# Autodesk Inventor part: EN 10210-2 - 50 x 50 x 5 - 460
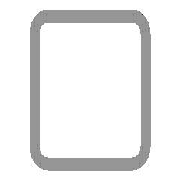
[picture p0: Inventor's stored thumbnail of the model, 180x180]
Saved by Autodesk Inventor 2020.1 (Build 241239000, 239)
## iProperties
_CCFamilyMember: 16
_CCFamilyDisplayName: DIN EN 10210-2 (USAS B17.1 quadratisch) - Rohrleitung — In Klammern angegebene Größen wurden aufgehoben
_FrameMemberDoc: Frame Member File
_Version: 15.0.0
_GetPNFromCC: 1
IsCustomPart: 1
Created: 2019-01
Part Number: EN 10210-2 - 50 x 50 x 5 - 460
Material: Stahl, weich
Description: Rohrleitung
Document SubType Name: Modeling
Standard: DIN
Designer: lutzd
Standard Revision: 2006-07
Standards Organization: DIN
Language: de-DE
Size Designation: 50 x 50 x 5
Categories: <MemberInstance><Categories><Category DisplayName="Profile" InternalName="089c4875-fa83-4c05-b084-43b9cc11f5ed" Mnemonic="GRDR"><CategoryParameter DisplayName="
Stock Number: 50 x 50 x 5
Mass: 3150.31 g
Surface Area: 1575.45 cm^2
Volume: 401.313 cm^3
Density: 7.85 g/cm^3
Appearance: Halbpoliert
G_L: 460,000 mm
G_W: 50,000 mm
G_H: 50,000 mm
DocNumber: ADSK-014081
Folder: .
Dimensions: 50x50x460 mm
Mass: 3,15 kg
+C3927D04-EFA9-4B3D-8386-313517081704+SCHNITTDETAIL1: Schnittwinkel 90,00 grd
Title: Profil-Bauteil
Author: lutzd
Revision Number: -
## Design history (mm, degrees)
node "Startebene"
node "Endebene"
sketch "Skizze"
  geometry: L1 (-25, -17.5)-(-25, 17.5); L2 (-17.5, 25)-(17.5, 25); L3 (25, 17.5)-(25, -17.5); L4 (17.5, -25)-(-17.5, -25); L5 (-15, 20)-(15, 20); L6 (20, 15)-(20, -15); L7 (15, -20)-(-15, -20); L8 (-20, -15)-(-20, 15); L9 (0, 37.175)-(0, -37.175) reference; L10 (-37.175, 0)-(37.175, 0) reference; A1 r 7.5 centre (-17.5, -17.5) between (-25, -17.5) and (-17.5, -25); A2 r 7.5 centre (-17.5, 17.5) between (-17.5, 25) and (-25, 17.5); A3 r 7.5 centre (17.5, 17.5) between (25, 17.5) and (17.5, 25); A4 r 7.5 centre (17.5, -17.5) between (17.5, -25) and (25, -17.5); A5 r 5 centre (-15, -15) between (-20, -15) and (-15, -20); A6 r 5 centre (-15, 15) between (-15, 20) and (-20, 15); A7 r 5 centre (15, 15) between (20, 15) and (15, 20); A8 r 5 centre (15, -15) between (15, -20) and (20, -15)
  constraints: 16 end point, 16 point on circle, 16 tangent, 8 centre point, 6 equal radius, 4 parallel, 2 perpendicular, 2 other
  dimensions: "d7" = 7.5 radius of A1 (= G_IR); "d10" = 50 distance between parallel lines of L2 L4 (= G_H); "d11" = 50 distance between parallel lines of L1 L3 (= G_W); "d12" = 5 distance between parallel lines of L3 L6 (= G_T); "d15" = 25 distance between parallel lines of L2 L10 (= 0.5 x d10); "d16" = 25 distance between parallel lines of L9 L3 (= 0.5 x d11); "d19" = 5 radius of A5 (= G_T); "d20" = 5 distance between parallel lines of L4 L7 (= G_T)
extrude "Körper" new body sketch "Skizze" stored distance "d3" = 460 (= G_L); taper "d4" = 0 deg
node "Driven Length"
  sketch "Sketch3"
    geometry: L1 (0, 0)-(10, 0) reference
    constraints: 2 end point, 1 horizontal
  workplane "Work Plane3"
  sketch "Sketch4"
    geometry: L1 (-2, 25)-(12, 25) reference; L2 (-2, 485)-(12, 485) reference
    dimensions: "d18" = 460 distance between parallel lines of L1 L2 (derived)
workplane "Arbeitsebene4"
feature "Trennen1"
sketch "Skizze5"
  geometry: L1 (0, -35)-(0, 0) reference; L2 (0, -17.5)-(321, -17.5); 3 further points
  constraints: 2 end point, 1 coincident, 1 horizontal, 1 midpoint, 1 point on line
  dimensions: "d21" = 41 distance of point (280, -17.5) point (321, -17.5); "d22" = 280 distance from line of L1 point (280, -17.5)
hole "Bohrung1" sketch "Skizze5" at (321, -17.5), (280, -17.5) diameter "d23" = 6.647; stored, may be unused: countersink angle "d27" = 90 deg, drill point angle "d29" = 118 deg; dims "d24" = 16, "d25" = 4, "d26" = 2, "d28" = 8
body "Solid1"
other parameters: "G_W" = 50 [user parameter; used in 1 equation term], "G_H" = 50 [user parameter; used in 1 equation term], "G_T" = 5 [user parameter; used in 3 equation terms], "G_IR" = 7.5 [user parameter; used in 1 equation term], "G_L" = 460 (= d18) [user parameter; used in 1 equation term], "G_OFFSET_START" = -25 [user parameter; used in 1 equation term], "G_OFFSET_END" = 0 [user parameter; used in 1 equation term], "d13" = 25 (= -G_OFFSET_START), "d14" = 485 (= G_OFFSET_END + B_L), "B_L" = 485 [user parameter; used in 1 equation term], "d17" = 90 deg
